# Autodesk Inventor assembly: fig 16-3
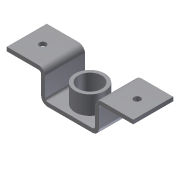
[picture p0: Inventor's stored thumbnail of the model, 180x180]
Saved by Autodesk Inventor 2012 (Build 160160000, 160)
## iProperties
Created: 2004-07
Part Number: fig 16-3
Document SubType Name: Weldment
Designer: CADCIM Technologies
Manufacturer: Standard
Standards Organization: Custom
Author: CADCIM Technologies
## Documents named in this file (3)
- C:\Users\CadCim\Documents\SAILESH\inventor-2011-fact-prt\c16-inv-2011-prt\c16_inv_2012_prt\fig 16-3.iam
- C:\Users\CadCim\Documents\SAILESH\inventor-2011-fact-prt\c16-inv-2011-prt\Bracket.ipt
- C:\Users\CadCim\Documents\SAILESH\inventor-2011-fact-prt\c16-inv-2011-prt\cylinder.ipt
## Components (2 placed, 2 different names)
1. Bracket:1 — Insert:1
2. cylinder:1 — Insert:1
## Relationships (1: Insert 1)
- Insert:1: Bracket:1 ↔ cylinder:1
